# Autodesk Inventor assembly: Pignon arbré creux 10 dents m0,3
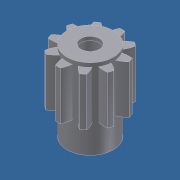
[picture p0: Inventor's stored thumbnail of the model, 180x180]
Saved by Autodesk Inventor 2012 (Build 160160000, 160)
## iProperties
Created: 2011-10
Part Number: Pignon arbré creux 10 dents m0,3
Document SubType Name: Assembly
Designer: Laur
Author: Laur
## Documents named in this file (3)
- D:\Formulaire\Sujet CIM 2012\Modélisation_7970_shimano\Pignon arbré creux 10 dents m0,3.iam
- D:\Formulaire\Sujet CIM 2012\Modélisation_7970_shimano\arbre creux inter.ipt
- D:\Formulaire\Sujet CIM 2012\Modélisation_7970_shimano\Mobile intermédiaire 37 dents m0,25 - 10 dents m0,3\Design Accelerator\Engrenages cylindriques2.iam
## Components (2 placed, 2 different names)
1. arbre creux inter:1 — Placage:1, Placage:2
2. Engrenages cylindriques:1 [sub-assembly] — Placage:1, Placage:2
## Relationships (2: Mate 2)
- Placage:1 [Mate]: arbre creux inter:1 ↔ Engrenages cylindriques:1
- Placage:2 [Mate]: arbre creux inter:1 ↔ Engrenages cylindriques:1
